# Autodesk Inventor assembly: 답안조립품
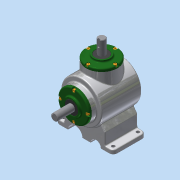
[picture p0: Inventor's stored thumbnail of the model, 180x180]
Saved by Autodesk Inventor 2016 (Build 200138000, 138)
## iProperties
Created: 2018-08
Part Number: 답안조립품
Material: 일반
Document SubType Name: Assembly
Designer: 605-11
Author: 605-11
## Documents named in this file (13)
- C:\Users\605-11\Desktop\480807V1030\답안조립품.iam
- C:\Users\605-11\Desktop\480807V1030\메인 축.ipt
- 메인 축.ipt
- C:\Users\605-11\Desktop\480807V1030\베어링 6203.ipt
- C:\Users\605-11\Desktop\480807V1030\오일실 17 32 8.ipt
- C:\Users\605-11\Desktop\480807V1030\본체.ipt
- C:\Users\605-11\Desktop\480807V1030\키 5x5.ipt
- C:\Users\605-11\Desktop\480807V1030\커버.ipt
- C:\Users\605-11\Desktop\480807V1030\볼트 M4.ipt
- C:\Users\605-11\Desktop\480807V1030\서브 베벨기어.ipt
- C:\Users\605-11\Desktop\480807V1030\서브 축.ipt
- 서브 축.ipt
- C:\Users\605-11\Desktop\480807V1030\키 4x4.ipt
